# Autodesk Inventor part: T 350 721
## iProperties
Company: Mayer & Müller AG Schaltgeräte
Created: 2005-06
Part Number: T 350 721
Material: 2.0060
Document SubType Name: Modeling
Designer: I.Baliuc
Manufacturer: Standard
Standards Organization: Custom
Description: Kontakt
Density: 8.94 g/cm^3
Author: T.Messerschmitt
Revision Number: 350721
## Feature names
1. Drehung1 [Revolution]
2. Rundung1 [Fillet]
